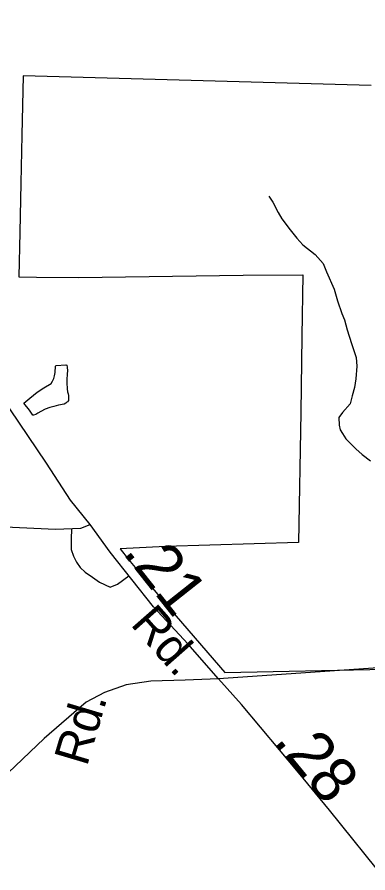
# Model space of a CAD drawing. Extents: x 2001466 to 31450019, y -30647475 to 847247.
# Drawn here: x 2195300 to 2197224, y 765114 to 769809 of the extents above; entities that cross this region are included whole.
import ezdxf

# ---------------------------------------------------------------- set-up
doc = ezdxf.new("R2010")
doc.units = 0
for name, color, linetype in [('Exist Boundary Political City Limit New', 7, 'Continuous'), ('Exist Hydrographic Misc Water Feature', 7, 'Continuous'), ('Exist Road Non-System Type 51', 7, 'Continuous'), ('Exist Road Primary NC Attributed', 7, 'Continuous'), ('Exist Road Primary NC Label', 7, 'Continuous'), ('Exist Road Primary NC Service Mileage Hundredths English Label', 7, 'Continuous'), ('Exist Road Secondary Type 51 Attributed', 7, 'Continuous'), ('Exist Road Secondary Type 51 Label', 7, 'Continuous'), ('Map Preparation Boundary City Limit Buffer Line', 7, 'Continuous')]:
    doc.layers.add(name, color=color, linetype=linetype)

msp = doc.modelspace()

# ---------------------------------------------------------------- linework, layer by layer
at = {"layer": 'Exist Boundary Political City Limit New'}
msp.add_lwpolyline([(2197241.8, 769432.8), (2195332.5, 769486.7), (2195326, 769161.4), (2195319.2, 768898.2), (2195313.8, 768628.8), (2195308.2, 768384.7), (2195406, 768382.1), (2195636.8, 768380.2), (2196539.8, 768392.9), (2196867.5, 768395.6), (2196861.8, 768057.6), (2196856, 767638.9), (2196843.8, 766926.6), (2196113, 766903.7), (2195864.5, 766891.6), (2195910.8, 766832.9), (2195965.5, 766766.6), (2196137.5, 766561.9), (2196171.2, 766521.8), (2196438.2, 766213.7), (2197322.5, 766231.1)], dxfattribs=at)
at = {"layer": 'Exist Hydrographic Misc Water Feature'}
for points in [[(2196680.7, 768826.9), (2196703.1, 768793.1), (2196731.6, 768737.3), (2196751.5, 768701.4), (2196798.2, 768642), (2196834.3, 768596), (2196866.7, 768560.3), (2196935, 768507), (2196977.4, 768457.2), (2196995.7, 768411.4), (2197038.3, 768315.7), (2197056.6, 768251.7), (2197081.2, 768181.9), (2197095.5, 768148.1), (2197109.5, 768092.4), (2197134.3, 768018.5), (2197158.7, 767940.6), (2197162.8, 767894.5), (2197157.7, 767824.7), (2197150.1, 767776.8), (2197138.2, 767730.7), (2197126.5, 767686.6), (2197084.9, 767640.2), (2197064.8, 767612), (2197065.2, 767570.1), (2197071.4, 767544), (2197083.9, 767524.3), (2197101.9, 767494.4), (2197133.9, 767464.8), (2197158.3, 767440.8), (2197192.5, 767408.9), (2197238.5, 767373.5)], [(2195572.2, 767801.8), (2195574.5, 767769.8), (2195576.9, 767753.6), (2195578.8, 767742), (2195580.8, 767731.9), (2195581, 767719.7), (2195581.2, 767705.9), (2195576.9, 767697.6), (2195573.2, 767695.7), (2195567.1, 767689.8), (2195557, 767685.6), (2195527.1, 767679.6), (2195501.5, 767673.3), (2195479.1, 767667.3), (2195453.3, 767657.1), (2195429.5, 767644.8), (2195413.3, 767636.7), (2195401.4, 767628.8), (2195389.7, 767624.5), (2195385.4, 767624.3), (2195367.6, 767652.6), (2195337.2, 767690), (2195369.2, 767718.4), (2195409, 767750.6), (2195446.5, 767774.9), (2195486.3, 767799.3), (2195494.3, 767811.1), (2195500.4, 767825.2), (2195503.9, 767841.3), (2195508.2, 767859.3), (2195509.5, 767893.2), (2195513.8, 767897.4), (2195567.5, 767901.4), (2195571.8, 767899.6), (2195573.7, 767887.6), (2195575.9, 767867.8), (2195574.1, 767851.8), (2195572.2, 767819.6), (2195572.2, 767801.8)]]:
    msp.add_lwpolyline(points, dxfattribs=at)
at = {"layer": 'Exist Road Non-System Type 51'}
msp.add_line((2197335.1, 766242.1), (2196403.3, 766178.3), dxfattribs=at)
msp.add_lwpolyline([(2195598.5, 767002.6), (2195595.5, 766943.2), (2195595.5, 766888.6), (2195608.4, 766851.2), (2195625.7, 766818.2), (2195645.8, 766789.4), (2195673.1, 766763.6), (2195713.3, 766736.2), (2195750.6, 766708.9), (2195809.5, 766681.6), (2195851.1, 766697.5), (2195913.3, 766743.8)], dxfattribs=at)
at = {"layer": 'Exist Road Primary NC Attributed'}
for points in [[(2195700.6, 767025.5), (2195592.3, 767158.5), (2195459.9, 767361.6), (2195259.6, 767659), (2195067.5, 768007.7), (2194854.6, 768386.7), (2194640.6, 768788.8), (2194513, 769028.6), (2194361.8, 769296.7), (2194235.1, 769499.8), (2193992.9, 769849.6), (2193698.3, 770241.2), (2193542.4, 770436), (2193264.6, 770772.1), (2193021.3, 771081), (2192715.3, 771477.9)], [(2196403.3, 766178.3), (2196235.3, 766370), (2196048.5, 766573.1), (2195810.5, 766873.6), (2195700.6, 767025.5)], [(2197337.2, 765055.8), (2197013.3, 765456.9), (2196842.2, 765665.2), (2196529.9, 766037), (2196403.3, 766178.3)]]:
    msp.add_lwpolyline(points, dxfattribs=at)
at = {"layer": 'Exist Road Secondary Type 51 Attributed'}
for points in [[(2190686.8, 768010.8), (2190928.6, 768015), (2191001.8, 768000.3), (2191139.9, 767956.4), (2191351.3, 767868.4), (2192007.4, 767552.2), (2192572.4, 767277.8), (2192906.2, 767118.7), (2193000.4, 767091.4), (2193130.2, 767078.9), (2193448.3, 767064.2), (2193764.3, 767049.5), (2194995.9, 767022.3), (2195510.7, 766999.3), (2195648.3, 767004.5), (2195700.6, 767025.5)], [(2196403.3, 766178.3), (2196221.2, 766171), (2196033.9, 766164.7), (2195897.3, 766144.8), (2195779.1, 766104), (2195677.6, 766049.5), (2195447.9, 765850.6), (2195251.2, 765663.2), (2194899.1, 765348), (2194786.1, 765282), (2194679.3, 765242.2), (2194582, 765221.3), (2194282.2, 765187.8), (2194041.6, 765171), (2193393.3, 765121.8), (2193126.5, 765100.8)]]:
    msp.add_lwpolyline(points, dxfattribs=at)
at = {"layer": 'Map Preparation Boundary City Limit Buffer Line'}
msp.add_lwpolyline([(2197241.8, 769432.8), (2195332.5, 769486.7), (2195326, 769161.4), (2195319.2, 768898.2), (2195313.8, 768628.8), (2195308.2, 768384.7), (2195406, 768382.1), (2195636.8, 768380.2), (2196539.8, 768392.9), (2196867.5, 768395.6), (2196861.8, 768057.6), (2196856, 767638.9), (2196843.8, 766926.6), (2196113, 766903.7), (2195864.5, 766891.6), (2195910.8, 766832.9), (2195965.5, 766766.6), (2196137.5, 766561.9), (2196171.2, 766521.8), (2196438.2, 766213.7), (2197322.5, 766231.1)], dxfattribs=at)

# ---------------------------------------------------------------- texts
at = {"layer": 'Exist Road Primary NC Label'}
msp.add_text('Rd.', height=190, rotation=311.3222, dxfattribs=at).set_placement((2195916.8, 766476.4))
at = {"layer": 'Exist Road Primary NC Service Mileage Hundredths English Label'}
for s, rotation, p in [('.21', 308.3835, (2195874.4, 766869.5)), ('.28', 309.3867, (2196702.9, 765835))]:
    msp.add_text(s, height=250, rotation=rotation, dxfattribs=at).set_placement(p)
at = {"layer": 'Exist Road Secondary Type 51 Label'}
msp.add_text('Rd.', height=190, rotation=73.4138, dxfattribs=at).set_placement((2195682.1, 765693))

doc.saveas('drawing.dxf')
